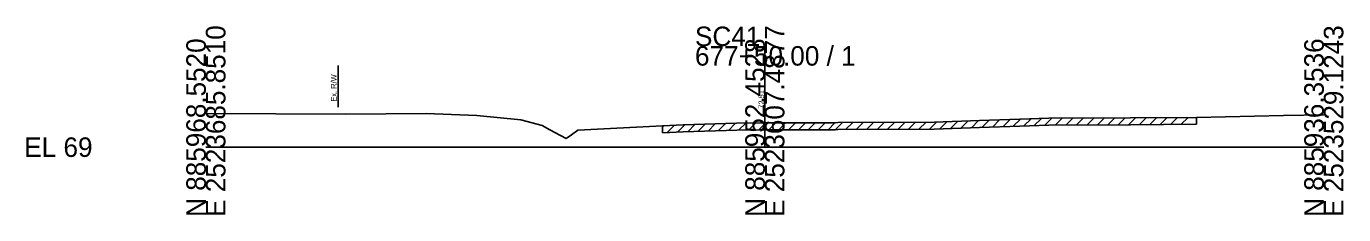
# Model space of a CAD drawing. Extents: x -26 to 183, y -10 to 24021.
# Drawn here: x -25.7 to 162.8, y 9990.3 to 10017.3 of the extents above; entities that cross this region are included whole.
import ezdxf

# ---------------------------------------------------------------- set-up
doc = ezdxf.new("R2010")
doc.units = 0
for name, color, linetype in [('RD_GPK_XS_Cell', 7, 'Continuous'), ('RD_XS_ExGround', 7, 'Continuous'), ('RD_XS_ExPaveRet', 7, 'Continuous'), ('RD_XS_ExRW', 7, 'Continuous'), ('RD_XS_TX_Elev_EX', 7, 'Continuous')]:
    doc.layers.add(name, color=color, linetype=linetype)

msp = doc.modelspace()

# ---------------------------------------------------------------- linework, layer by layer
at = {"layer": 'RD_GPK_XS_Cell'}
for p, q in [((80, 10000), (80, 10014.5)), ((0, 10000), (80, 10000)), ((80, 10000), (160, 10000))]:
    msp.add_line(p, q, dxfattribs=at)
at = {"layer": 'RD_XS_ExGround'}
for p, q in [((0, 10004.83), (20.05, 10004.74)), ((20.05, 10004.74), (31.51, 10004.81)), ((31.51, 10004.81), (38.8, 10004.52)), ((38.8, 10004.52), (45.09, 10003.9)), ((45.09, 10003.9), (48.15, 10003.1)), ((90.44, 10003.52), (104.25, 10003.59)), ((104.25, 10003.59), (110.73, 10003.82)), ((110.73, 10003.82), (116.51, 10004.03)), ((116.51, 10004.03), (120.65, 10004.16)), ((120.65, 10004.16), (132.34, 10004.19)), ((132.34, 10004.19), (141.78, 10004.28)), ((141.78, 10004.28), (154.21, 10004.56)), ((154.21, 10004.56), (160, 10004.66)), ((48.15, 10003.1), (49.25, 10002.49)), ((49.25, 10002.49), (51.57, 10001.23)), ((51.57, 10001.23), (52.32, 10001.76)), ((52.32, 10001.76), (53.22, 10002.44)), ((53.22, 10002.44), (61.61, 10002.85)), ((61.61, 10002.85), (65.37, 10003.08)), ((65.37, 10003.08), (68.32, 10003.2)), ((68.32, 10003.2), (75.95, 10003.42)), ((75.95, 10003.42), (79.37, 10003.51)), ((79.37, 10003.51), (80, 10003.51)), ((80, 10003.51), (80.8, 10003.51)), ((80.8, 10003.51), (90.06, 10003.49)), ((90.06, 10003.49), (90.44, 10003.52))]:
    msp.add_line(p, q, dxfattribs=at)
at = {"layer": 'RD_XS_ExPaveRet'}
for p, q in [((93.06, 10002.54), (94.07, 10003.54)), ((94.56, 10002.54), (95.57, 10003.55)), ((96.06, 10002.55), (97.07, 10003.56)), ((97.56, 10002.56), (98.57, 10003.56)), ((99.06, 10002.57), (100.07, 10003.57)), ((100.56, 10002.57), (101.57, 10003.58)), ((102.06, 10002.58), (103.07, 10003.59)), ((103.56, 10002.59), (104.58, 10003.6)), ((105.06, 10002.62), (106.1, 10003.66)), ((106.56, 10002.67), (107.6, 10003.71)), ((108.06, 10002.73), (109.1, 10003.76)), ((109.56, 10002.78), (110.6, 10003.81)), ((111.06, 10002.83), (112.1, 10003.87)), ((112.56, 10002.89), (113.6, 10003.92)), ((114.06, 10002.94), (115.1, 10003.98)), ((115.56, 10003), (116.6, 10004.04)), ((117.06, 10003.05), (118.1, 10004.08)), ((118.56, 10003.1), (119.6, 10004.13)), ((120.06, 10003.14), (121.08, 10004.16)), ((121.56, 10003.17), (122.57, 10004.17)), ((123.06, 10003.17), (124.07, 10004.17)), ((124.56, 10003.17), (125.57, 10004.17)), ((126.06, 10003.18), (127.07, 10004.18)), ((127.56, 10003.18), (128.57, 10004.18)), ((129.06, 10003.18), (130.07, 10004.19)), ((130.56, 10003.19), (131.57, 10004.19)), ((132.06, 10003.19), (133.07, 10004.2)), ((133.56, 10003.2), (134.57, 10004.21)), ((135.06, 10003.22), (136.07, 10004.22)), ((136.56, 10003.23), (137.57, 10004.24)), ((138.06, 10003.24), (139.07, 10004.25)), ((139.56, 10003.26), (140.57, 10004.26)), ((141.78, 10004.28), (141.78, 10003.28)), ((65.37, 10002.86), (65.59, 10003.09)), ((65.37, 10003.08), (65.37, 10002.08)), ((65.37, 10002.08), (68.29, 10002.2)), ((66.02, 10002.11), (67.07, 10003.15)), ((67.5, 10002.17), (68.54, 10003.21)), ((68.29, 10002.2), (75.98, 10002.42)), ((68.97, 10002.22), (70, 10003.25)), ((70.42, 10002.26), (71.45, 10003.29)), ((71.88, 10002.3), (72.91, 10003.33)), ((73.33, 10002.35), (74.36, 10003.38)), ((74.79, 10002.39), (75.82, 10003.42)), ((75.98, 10002.42), (79.38, 10002.51)), ((76.24, 10002.43), (77.27, 10003.45)), ((77.7, 10002.47), (78.72, 10003.49)), ((79.15, 10002.5), (80.15, 10003.51)), ((79.38, 10002.51), (80, 10002.51)), ((80, 10002.51), (80.8, 10002.51)), ((80.57, 10002.51), (81.57, 10003.51)), ((80.8, 10002.51), (90.06, 10002.49)), ((81.98, 10002.51), (82.98, 10003.51)), ((83.39, 10002.5), (84.39, 10003.5)), ((84.8, 10002.5), (85.8, 10003.5)), ((86.21, 10002.5), (87.21, 10003.5)), ((87.63, 10002.5), (88.62, 10003.49)), ((89.04, 10002.49), (90.04, 10003.49)), ((90.06, 10002.49), (91.1, 10003.53)), ((90.06, 10002.49), (90.44, 10002.52)), ((90.44, 10002.52), (104.25, 10002.59)), ((91.56, 10002.53), (92.57, 10003.54)), ((104.25, 10002.59), (110.73, 10002.82)), ((110.73, 10002.82), (116.51, 10003.03)), ((116.51, 10003.03), (120.65, 10003.16)), ((120.65, 10003.16), (132.34, 10003.19)), ((132.34, 10003.19), (141.78, 10003.28))]:
    msp.add_line(p, q, dxfattribs=at)
at = {"layer": 'RD_XS_ExRW'}
msp.add_line((18.95, 10011.74), (18.95, 10005.74), dxfattribs=at)

# ---------------------------------------------------------------- texts
at = {"layer": 'RD_GPK_XS_Cell'}
for s, p in [('E 2523685.8510', (2.8, 9990)), ('E 2523607.4877', (82.8, 9990)), ('E 2523529.1243', (162.8, 9990)), ('N 885968.5520', (0, 9990)), ('N 885952.4528', (80, 9990)), ('N 885936.3536', (160, 9990))]:
    msp.add_text(s, height=2.8, rotation=90, dxfattribs=at).set_placement(p)
for s, p in [('SC41', (70, 10014.5)), ('677+50.00 / 1', (70, 10011.7)), ('EL 69', (-26, 9998.6))]:
    msp.add_text(s, height=2.8, dxfattribs=at).set_placement(p)
at = {"layer": 'RD_XS_ExRW'}
msp.add_text('Ex. R/W ', height=0.8, rotation=90, dxfattribs=at).set_placement((18.7, 10006.53))
at = {"layer": 'RD_XS_TX_Elev_EX'}
msp.add_text('72.51', height=0.8, rotation=90, dxfattribs=at).set_placement((79.9, 10005.51))

doc.saveas('drawing.dxf')
